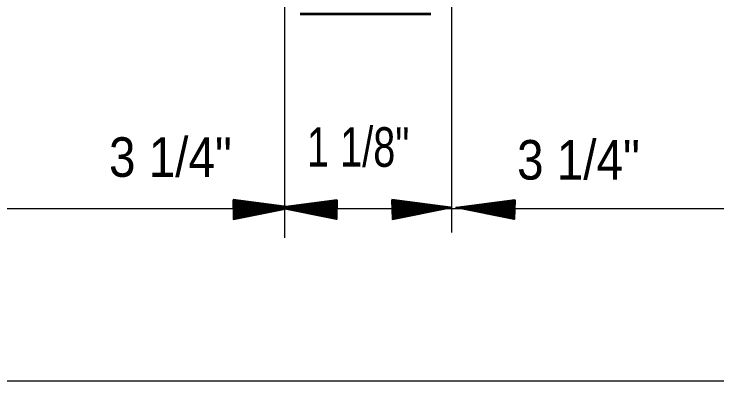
# Model space of a CAD drawing. Extents: x 895.6 to 930.4, y -2278.6 to -2254.7.
# Drawn here: x 901.427 to 903.71, y -2274.643 to -2273.45 of the extents above; entities that cross this region are included whole.
import ezdxf

# ---------------------------------------------------------------- set-up
doc = ezdxf.new("R2010")
doc.units = 0
doc.header["$LTSCALE"] = 0.051
doc.layers.add('1', color=7, linetype='Continuous', lineweight=70)
doc.layers.add('3', color=7, linetype='Continuous', lineweight=40)

msp = doc.modelspace()

# ---------------------------------------------------------------- hatches: boundary and pattern name
at = {"layer": '3'}
for points in [[(902.13817, -2274.05375), (902.14025, -2274.117), (902.32875, -2274.07892), (902.32875, -2274.07892)], [(902.13917, -2274.057), (902.141, -2274.11375), (902.31058, -2274.07958), (902.31058, -2274.07958)], [(902.14, -2274.05975), (902.14167, -2274.11092), (902.29433, -2274.08008), (902.29433, -2274.08008)], [(902.14083, -2274.06233), (902.14233, -2274.10825), (902.27967, -2274.08058), (902.27967, -2274.08058)], [(902.14142, -2274.06442), (902.14292, -2274.10583), (902.2665, -2274.081), (902.2665, -2274.081)], [(902.14225, -2274.06658), (902.14342, -2274.10383), (902.25467, -2274.08133), (902.25467, -2274.08133)], [(902.14267, -2274.06842), (902.14375, -2274.10208), (902.244, -2274.08183), (902.244, -2274.08183)], [(902.14325, -2274.07), (902.14417, -2274.10025), (902.23425, -2274.082), (902.23425, -2274.082)], [(902.14358, -2274.0715), (902.14458, -2274.09883), (902.22567, -2274.0825), (902.22567, -2274.0825)], [(902.14408, -2274.07292), (902.145, -2274.0975), (902.21792, -2274.08258), (902.21792, -2274.08258)], [(902.476, -2274.05375), (902.47392, -2274.117), (902.28542, -2274.07892), (902.28542, -2274.07892)], [(902.475, -2274.057), (902.47317, -2274.11375), (902.30358, -2274.07958), (902.30358, -2274.07958)], [(902.47417, -2274.05975), (902.4725, -2274.11092), (902.31983, -2274.08008), (902.31983, -2274.08008)], [(902.47333, -2274.06233), (902.47183, -2274.10825), (902.3345, -2274.08058), (902.3345, -2274.08058)], [(902.47275, -2274.06442), (902.47125, -2274.10583), (902.34767, -2274.081), (902.34767, -2274.081)], [(902.47192, -2274.06658), (902.47075, -2274.10383), (902.3595, -2274.08133), (902.3595, -2274.08133)], [(902.4715, -2274.06842), (902.47042, -2274.10208), (902.37017, -2274.08183), (902.37017, -2274.08183)], [(902.47092, -2274.07), (902.47, -2274.10025), (902.37992, -2274.082), (902.37992, -2274.082)], [(902.47058, -2274.0715), (902.46958, -2274.09883), (902.3885, -2274.0825), (902.3885, -2274.0825)], [(902.47008, -2274.07292), (902.46917, -2274.0975), (902.39625, -2274.08258), (902.39625, -2274.08258)], [(902.65433, -2274.05375), (902.65642, -2274.117), (902.84492, -2274.07892), (902.84492, -2274.07892)], [(902.65533, -2274.057), (902.65717, -2274.11375), (902.82675, -2274.07958), (902.82675, -2274.07958)], [(902.65617, -2274.05975), (902.65783, -2274.11092), (902.8105, -2274.08008), (902.8105, -2274.08008)], [(902.657, -2274.06233), (902.6585, -2274.10825), (902.79583, -2274.08058), (902.79583, -2274.08058)], [(902.65758, -2274.06442), (902.65908, -2274.10583), (902.78267, -2274.081), (902.78267, -2274.081)], [(902.65842, -2274.06658), (902.65958, -2274.10383), (902.77083, -2274.08133), (902.77083, -2274.08133)], [(902.65883, -2274.06842), (902.65992, -2274.10208), (902.76017, -2274.08183), (902.76017, -2274.08183)], [(902.65942, -2274.07), (902.66033, -2274.10025), (902.75042, -2274.082), (902.75042, -2274.082)], [(902.65975, -2274.0715), (902.66075, -2274.09883), (902.74183, -2274.0825), (902.74183, -2274.0825)], [(902.66025, -2274.07292), (902.66117, -2274.0975), (902.73408, -2274.08258), (902.73408, -2274.08258)], [(903.05358, -2274.05375), (903.0515, -2274.117), (902.863, -2274.07892), (902.863, -2274.07892)], [(903.05258, -2274.057), (903.05075, -2274.11375), (902.88117, -2274.07958), (902.88117, -2274.07958)], [(903.05175, -2274.05975), (903.05008, -2274.11092), (902.89742, -2274.08008), (902.89742, -2274.08008)], [(903.05092, -2274.06233), (903.04942, -2274.10825), (902.91208, -2274.08058), (902.91208, -2274.08058)], [(903.05033, -2274.06442), (903.04883, -2274.10583), (902.92525, -2274.081), (902.92525, -2274.081)], [(903.0495, -2274.06658), (903.04833, -2274.10383), (902.93708, -2274.08133), (902.93708, -2274.08133)], [(903.04908, -2274.06842), (903.048, -2274.10208), (902.94775, -2274.08183), (902.94775, -2274.08183)], [(903.0485, -2274.07), (903.04758, -2274.10025), (902.9575, -2274.082), (902.9575, -2274.082)], [(903.04817, -2274.0715), (903.04717, -2274.09883), (902.96608, -2274.0825), (902.96608, -2274.0825)], [(903.04767, -2274.07292), (903.04675, -2274.0975), (902.97383, -2274.08258), (902.97383, -2274.08258)], [(902.1445, -2274.07417), (902.14525, -2274.09608), (902.21083, -2274.08292), (902.21083, -2274.08292)], [(902.14475, -2274.07525), (902.1455, -2274.095), (902.20458, -2274.08325), (902.20458, -2274.08325)], [(902.14517, -2274.07617), (902.14567, -2274.09408), (902.19875, -2274.08333), (902.19875, -2274.08333)], [(902.1455, -2274.07717), (902.14592, -2274.09317), (902.19383, -2274.08342), (902.19383, -2274.08342)], [(902.14567, -2274.07792), (902.14617, -2274.09233), (902.18917, -2274.08358), (902.18917, -2274.08358)], [(902.14592, -2274.07858), (902.14625, -2274.09167), (902.18508, -2274.08392), (902.18508, -2274.08392)], [(902.14608, -2274.07925), (902.1465, -2274.09108), (902.18133, -2274.084), (902.18133, -2274.084)], [(902.14625, -2274.07992), (902.14658, -2274.09042), (902.17808, -2274.08408), (902.17808, -2274.08408)], [(902.1465, -2274.08025), (902.14675, -2274.08983), (902.17508, -2274.08408), (902.17508, -2274.08408)], [(902.14667, -2274.08067), (902.14692, -2274.08933), (902.17242, -2274.08408), (902.17242, -2274.08408)], [(902.14683, -2274.081), (902.14708, -2274.08867), (902.17, -2274.084), (902.17, -2274.084)], [(902.14683, -2274.08142), (902.14708, -2274.08833), (902.16783, -2274.08408), (902.16783, -2274.08408)], [(902.147, -2274.08183), (902.14725, -2274.088), (902.16583, -2274.08433), (902.16583, -2274.08433)], [(902.14708, -2274.082), (902.14733, -2274.08758), (902.16408, -2274.08425), (902.16408, -2274.08425)], [(902.46967, -2274.07417), (902.46892, -2274.09608), (902.40333, -2274.08292), (902.40333, -2274.08292)], [(902.46942, -2274.07525), (902.46867, -2274.095), (902.40958, -2274.08325), (902.40958, -2274.08325)], [(902.469, -2274.07617), (902.4685, -2274.09408), (902.41542, -2274.08333), (902.41542, -2274.08333)], [(902.46867, -2274.07717), (902.46825, -2274.09317), (902.42033, -2274.08342), (902.42033, -2274.08342)], [(902.4685, -2274.07792), (902.468, -2274.09233), (902.425, -2274.08358), (902.425, -2274.08358)], [(902.46825, -2274.07858), (902.46792, -2274.09167), (902.42908, -2274.08392), (902.42908, -2274.08392)], [(902.46808, -2274.07925), (902.46767, -2274.09108), (902.43283, -2274.084), (902.43283, -2274.084)], [(902.46792, -2274.07992), (902.46758, -2274.09042), (902.43608, -2274.08408), (902.43608, -2274.08408)], [(902.46767, -2274.08025), (902.46742, -2274.08983), (902.43908, -2274.08408), (902.43908, -2274.08408)], [(902.4675, -2274.08067), (902.46725, -2274.08933), (902.44175, -2274.08408), (902.44175, -2274.08408)], [(902.46733, -2274.081), (902.46708, -2274.08867), (902.44417, -2274.084), (902.44417, -2274.084)], [(902.46733, -2274.08142), (902.46708, -2274.08833), (902.44633, -2274.08408), (902.44633, -2274.08408)], [(902.46717, -2274.08183), (902.46692, -2274.088), (902.44833, -2274.08433), (902.44833, -2274.08433)], [(902.46708, -2274.082), (902.46683, -2274.08758), (902.45008, -2274.08425), (902.45008, -2274.08425)], [(902.66067, -2274.07417), (902.66142, -2274.09608), (902.727, -2274.08292), (902.727, -2274.08292)], [(902.66092, -2274.07525), (902.66167, -2274.095), (902.72075, -2274.08325), (902.72075, -2274.08325)], [(902.66133, -2274.07617), (902.66183, -2274.09408), (902.71492, -2274.08333), (902.71492, -2274.08333)], [(902.66167, -2274.07717), (902.66208, -2274.09317), (902.71, -2274.08342), (902.71, -2274.08342)], [(902.66183, -2274.07792), (902.66233, -2274.09233), (902.70533, -2274.08358), (902.70533, -2274.08358)], [(902.66208, -2274.07858), (902.66242, -2274.09167), (902.70125, -2274.08392), (902.70125, -2274.08392)], [(902.66225, -2274.07925), (902.66267, -2274.09108), (902.6975, -2274.084), (902.6975, -2274.084)], [(902.66242, -2274.07992), (902.66275, -2274.09042), (902.69425, -2274.08408), (902.69425, -2274.08408)], [(902.66267, -2274.08025), (902.66292, -2274.08983), (902.69125, -2274.08408), (902.69125, -2274.08408)], [(902.66283, -2274.08067), (902.66308, -2274.08933), (902.68858, -2274.08408), (902.68858, -2274.08408)], [(902.663, -2274.081), (902.66325, -2274.08867), (902.68617, -2274.084), (902.68617, -2274.084)], [(902.663, -2274.08142), (902.66325, -2274.08833), (902.684, -2274.08408), (902.684, -2274.08408)], [(902.66317, -2274.08183), (902.66342, -2274.088), (902.682, -2274.08433), (902.682, -2274.08433)], [(902.66325, -2274.082), (902.6635, -2274.08758), (902.68025, -2274.08425), (902.68025, -2274.08425)], [(903.04725, -2274.07417), (903.0465, -2274.09608), (902.98092, -2274.08292), (902.98092, -2274.08292)], [(903.047, -2274.07525), (903.04625, -2274.095), (902.98717, -2274.08325), (902.98717, -2274.08325)], [(903.04658, -2274.07617), (903.04608, -2274.09408), (902.993, -2274.08333), (902.993, -2274.08333)], [(903.04625, -2274.07717), (903.04583, -2274.09317), (902.99792, -2274.08342), (902.99792, -2274.08342)], [(903.04608, -2274.07792), (903.04558, -2274.09233), (903.00258, -2274.08358), (903.00258, -2274.08358)], [(903.04583, -2274.07858), (903.0455, -2274.09167), (903.00667, -2274.08392), (903.00667, -2274.08392)], [(903.04567, -2274.07925), (903.04525, -2274.09108), (903.01042, -2274.084), (903.01042, -2274.084)], [(903.0455, -2274.07992), (903.04517, -2274.09042), (903.01367, -2274.08408), (903.01367, -2274.08408)], [(903.04525, -2274.08025), (903.045, -2274.08983), (903.01667, -2274.08408), (903.01667, -2274.08408)], [(903.04508, -2274.08067), (903.04483, -2274.08933), (903.01933, -2274.08408), (903.01933, -2274.08408)], [(903.04492, -2274.081), (903.04467, -2274.08867), (903.02175, -2274.084), (903.02175, -2274.084)], [(903.04492, -2274.08142), (903.04467, -2274.08833), (903.02392, -2274.08408), (903.02392, -2274.08408)], [(903.04475, -2274.08183), (903.0445, -2274.088), (903.02592, -2274.08433), (903.02592, -2274.08433)], [(903.04467, -2274.082), (903.04442, -2274.08758), (903.02767, -2274.08425), (903.02767, -2274.08425)]]:
    msp.add_hatch(color=256, dxfattribs=at).paths.add_polyline_path(points)

# ---------------------------------------------------------------- linework, layer by layer
at = {"layer": '1', "lineweight": 25}
for p, q in [((902.30508, -2273.35175), (902.30508, -2274.17808)), ((902.84783, -2273.35175), (902.84783, -2274.16025)), ((900.23575, -2274.08225), (904.02683, -2274.08225)), ((900.23575, -2274.64308), (907.81792, -2274.64308))]:
    msp.add_line(p, q, dxfattribs=at)
at = {"layer": '1', "lineweight": 53}
msp.add_line((902.78058, -2273.45075), (902.3565, -2273.45075), dxfattribs=at)
at = {"layer": '3'}
for points in [[(902.13817, -2274.05375), (902.14025, -2274.117), (902.32875, -2274.07892), (902.32875, -2274.07892)], [(902.13917, -2274.057), (902.141, -2274.11375), (902.31058, -2274.07958), (902.31058, -2274.07958)], [(902.14, -2274.05975), (902.14167, -2274.11092), (902.29433, -2274.08008), (902.29433, -2274.08008)], [(902.14083, -2274.06233), (902.14233, -2274.10825), (902.27967, -2274.08058), (902.27967, -2274.08058)], [(902.14142, -2274.06442), (902.14292, -2274.10583), (902.2665, -2274.081), (902.2665, -2274.081)], [(902.14225, -2274.06658), (902.14342, -2274.10383), (902.25467, -2274.08133), (902.25467, -2274.08133)], [(902.14267, -2274.06842), (902.14375, -2274.10208), (902.244, -2274.08183), (902.244, -2274.08183)], [(902.14325, -2274.07), (902.14417, -2274.10025), (902.23425, -2274.082), (902.23425, -2274.082)], [(902.14358, -2274.0715), (902.14458, -2274.09883), (902.22567, -2274.0825), (902.22567, -2274.0825)], [(902.14408, -2274.07292), (902.145, -2274.0975), (902.21792, -2274.08258), (902.21792, -2274.08258)], [(902.476, -2274.05375), (902.47392, -2274.117), (902.28542, -2274.07892), (902.28542, -2274.07892)], [(902.475, -2274.057), (902.47317, -2274.11375), (902.30358, -2274.07958), (902.30358, -2274.07958)], [(902.47417, -2274.05975), (902.4725, -2274.11092), (902.31983, -2274.08008), (902.31983, -2274.08008)], [(902.47333, -2274.06233), (902.47183, -2274.10825), (902.3345, -2274.08058), (902.3345, -2274.08058)], [(902.47275, -2274.06442), (902.47125, -2274.10583), (902.34767, -2274.081), (902.34767, -2274.081)], [(902.47192, -2274.06658), (902.47075, -2274.10383), (902.3595, -2274.08133), (902.3595, -2274.08133)], [(902.4715, -2274.06842), (902.47042, -2274.10208), (902.37017, -2274.08183), (902.37017, -2274.08183)], [(902.47092, -2274.07), (902.47, -2274.10025), (902.37992, -2274.082), (902.37992, -2274.082)], [(902.47058, -2274.0715), (902.46958, -2274.09883), (902.3885, -2274.0825), (902.3885, -2274.0825)], [(902.47008, -2274.07292), (902.46917, -2274.0975), (902.39625, -2274.08258), (902.39625, -2274.08258)], [(902.65433, -2274.05375), (902.65642, -2274.117), (902.84492, -2274.07892), (902.84492, -2274.07892)], [(902.65533, -2274.057), (902.65717, -2274.11375), (902.82675, -2274.07958), (902.82675, -2274.07958)], [(902.65617, -2274.05975), (902.65783, -2274.11092), (902.8105, -2274.08008), (902.8105, -2274.08008)], [(902.657, -2274.06233), (902.6585, -2274.10825), (902.79583, -2274.08058), (902.79583, -2274.08058)], [(902.65758, -2274.06442), (902.65908, -2274.10583), (902.78267, -2274.081), (902.78267, -2274.081)], [(902.65842, -2274.06658), (902.65958, -2274.10383), (902.77083, -2274.08133), (902.77083, -2274.08133)], [(902.65883, -2274.06842), (902.65992, -2274.10208), (902.76017, -2274.08183), (902.76017, -2274.08183)], [(902.65942, -2274.07), (902.66033, -2274.10025), (902.75042, -2274.082), (902.75042, -2274.082)], [(902.65975, -2274.0715), (902.66075, -2274.09883), (902.74183, -2274.0825), (902.74183, -2274.0825)], [(902.66025, -2274.07292), (902.66117, -2274.0975), (902.73408, -2274.08258), (902.73408, -2274.08258)], [(903.05358, -2274.05375), (903.0515, -2274.117), (902.863, -2274.07892), (902.863, -2274.07892)], [(903.05258, -2274.057), (903.05075, -2274.11375), (902.88117, -2274.07958), (902.88117, -2274.07958)], [(903.05175, -2274.05975), (903.05008, -2274.11092), (902.89742, -2274.08008), (902.89742, -2274.08008)], [(903.05092, -2274.06233), (903.04942, -2274.10825), (902.91208, -2274.08058), (902.91208, -2274.08058)], [(903.05033, -2274.06442), (903.04883, -2274.10583), (902.92525, -2274.081), (902.92525, -2274.081)], [(903.0495, -2274.06658), (903.04833, -2274.10383), (902.93708, -2274.08133), (902.93708, -2274.08133)], [(903.04908, -2274.06842), (903.048, -2274.10208), (902.94775, -2274.08183), (902.94775, -2274.08183)], [(903.0485, -2274.07), (903.04758, -2274.10025), (902.9575, -2274.082), (902.9575, -2274.082)], [(903.04817, -2274.0715), (903.04717, -2274.09883), (902.96608, -2274.0825), (902.96608, -2274.0825)], [(903.04767, -2274.07292), (903.04675, -2274.0975), (902.97383, -2274.08258), (902.97383, -2274.08258)], [(902.1445, -2274.07417), (902.14525, -2274.09608), (902.21083, -2274.08292), (902.21083, -2274.08292)], [(902.14475, -2274.07525), (902.1455, -2274.095), (902.20458, -2274.08325), (902.20458, -2274.08325)], [(902.14517, -2274.07617), (902.14567, -2274.09408), (902.19875, -2274.08333), (902.19875, -2274.08333)], [(902.1455, -2274.07717), (902.14592, -2274.09317), (902.19383, -2274.08342), (902.19383, -2274.08342)], [(902.14567, -2274.07792), (902.14617, -2274.09233), (902.18917, -2274.08358), (902.18917, -2274.08358)], [(902.14592, -2274.07858), (902.14625, -2274.09167), (902.18508, -2274.08392), (902.18508, -2274.08392)], [(902.14608, -2274.07925), (902.1465, -2274.09108), (902.18133, -2274.084), (902.18133, -2274.084)], [(902.14625, -2274.07992), (902.14658, -2274.09042), (902.17808, -2274.08408), (902.17808, -2274.08408)], [(902.1465, -2274.08025), (902.14675, -2274.08983), (902.17508, -2274.08408), (902.17508, -2274.08408)], [(902.14667, -2274.08067), (902.14692, -2274.08933), (902.17242, -2274.08408), (902.17242, -2274.08408)], [(902.14683, -2274.081), (902.14708, -2274.08867), (902.17, -2274.084), (902.17, -2274.084)], [(902.14683, -2274.08142), (902.14708, -2274.08833), (902.16783, -2274.08408), (902.16783, -2274.08408)], [(902.147, -2274.08183), (902.14725, -2274.088), (902.16583, -2274.08433), (902.16583, -2274.08433)], [(902.14708, -2274.082), (902.14733, -2274.08758), (902.16408, -2274.08425), (902.16408, -2274.08425)], [(902.46967, -2274.07417), (902.46892, -2274.09608), (902.40333, -2274.08292), (902.40333, -2274.08292)], [(902.46942, -2274.07525), (902.46867, -2274.095), (902.40958, -2274.08325), (902.40958, -2274.08325)], [(902.469, -2274.07617), (902.4685, -2274.09408), (902.41542, -2274.08333), (902.41542, -2274.08333)], [(902.46867, -2274.07717), (902.46825, -2274.09317), (902.42033, -2274.08342), (902.42033, -2274.08342)], [(902.4685, -2274.07792), (902.468, -2274.09233), (902.425, -2274.08358), (902.425, -2274.08358)], [(902.46825, -2274.07858), (902.46792, -2274.09167), (902.42908, -2274.08392), (902.42908, -2274.08392)], [(902.46808, -2274.07925), (902.46767, -2274.09108), (902.43283, -2274.084), (902.43283, -2274.084)], [(902.46792, -2274.07992), (902.46758, -2274.09042), (902.43608, -2274.08408), (902.43608, -2274.08408)], [(902.46767, -2274.08025), (902.46742, -2274.08983), (902.43908, -2274.08408), (902.43908, -2274.08408)], [(902.4675, -2274.08067), (902.46725, -2274.08933), (902.44175, -2274.08408), (902.44175, -2274.08408)], [(902.46733, -2274.081), (902.46708, -2274.08867), (902.44417, -2274.084), (902.44417, -2274.084)], [(902.46733, -2274.08142), (902.46708, -2274.08833), (902.44633, -2274.08408), (902.44633, -2274.08408)], [(902.46717, -2274.08183), (902.46692, -2274.088), (902.44833, -2274.08433), (902.44833, -2274.08433)], [(902.46708, -2274.082), (902.46683, -2274.08758), (902.45008, -2274.08425), (902.45008, -2274.08425)], [(902.66067, -2274.07417), (902.66142, -2274.09608), (902.727, -2274.08292), (902.727, -2274.08292)], [(902.66092, -2274.07525), (902.66167, -2274.095), (902.72075, -2274.08325), (902.72075, -2274.08325)], [(902.66133, -2274.07617), (902.66183, -2274.09408), (902.71492, -2274.08333), (902.71492, -2274.08333)], [(902.66167, -2274.07717), (902.66208, -2274.09317), (902.71, -2274.08342), (902.71, -2274.08342)], [(902.66183, -2274.07792), (902.66233, -2274.09233), (902.70533, -2274.08358), (902.70533, -2274.08358)], [(902.66208, -2274.07858), (902.66242, -2274.09167), (902.70125, -2274.08392), (902.70125, -2274.08392)], [(902.66225, -2274.07925), (902.66267, -2274.09108), (902.6975, -2274.084), (902.6975, -2274.084)], [(902.66242, -2274.07992), (902.66275, -2274.09042), (902.69425, -2274.08408), (902.69425, -2274.08408)], [(902.66267, -2274.08025), (902.66292, -2274.08983), (902.69125, -2274.08408), (902.69125, -2274.08408)], [(902.66283, -2274.08067), (902.66308, -2274.08933), (902.68858, -2274.08408), (902.68858, -2274.08408)], [(902.663, -2274.081), (902.66325, -2274.08867), (902.68617, -2274.084), (902.68617, -2274.084)], [(902.663, -2274.08142), (902.66325, -2274.08833), (902.684, -2274.08408), (902.684, -2274.08408)], [(902.66317, -2274.08183), (902.66342, -2274.088), (902.682, -2274.08433), (902.682, -2274.08433)], [(902.66325, -2274.082), (902.6635, -2274.08758), (902.68025, -2274.08425), (902.68025, -2274.08425)], [(903.04725, -2274.07417), (903.0465, -2274.09608), (902.98092, -2274.08292), (902.98092, -2274.08292)], [(903.047, -2274.07525), (903.04625, -2274.095), (902.98717, -2274.08325), (902.98717, -2274.08325)], [(903.04658, -2274.07617), (903.04608, -2274.09408), (902.993, -2274.08333), (902.993, -2274.08333)], [(903.04625, -2274.07717), (903.04583, -2274.09317), (902.99792, -2274.08342), (902.99792, -2274.08342)], [(903.04608, -2274.07792), (903.04558, -2274.09233), (903.00258, -2274.08358), (903.00258, -2274.08358)], [(903.04583, -2274.07858), (903.0455, -2274.09167), (903.00667, -2274.08392), (903.00667, -2274.08392)], [(903.04567, -2274.07925), (903.04525, -2274.09108), (903.01042, -2274.084), (903.01042, -2274.084)], [(903.0455, -2274.07992), (903.04517, -2274.09042), (903.01367, -2274.08408), (903.01367, -2274.08408)], [(903.04525, -2274.08025), (903.045, -2274.08983), (903.01667, -2274.08408), (903.01667, -2274.08408)], [(903.04508, -2274.08067), (903.04483, -2274.08933), (903.01933, -2274.08408), (903.01933, -2274.08408)], [(903.04492, -2274.081), (903.04467, -2274.08867), (903.02175, -2274.084), (903.02175, -2274.084)], [(903.04492, -2274.08142), (903.04467, -2274.08833), (903.02392, -2274.08408), (903.02392, -2274.08408)], [(903.04475, -2274.08183), (903.0445, -2274.088), (903.02592, -2274.08433), (903.02592, -2274.08433)], [(903.04467, -2274.082), (903.04442, -2274.08758), (903.02767, -2274.08425), (903.02767, -2274.08425)]]:
    msp.add_lwpolyline(points, close=True, dxfattribs=at)

# ---------------------------------------------------------------- texts
at = {"layer": '1'}
for s, width, p in [('1 1/8"', 0.75, (902.3785, -2273.94667)), ('3 1/4"', 0.9, (901.73525, -2273.97933)), ('3 1/4"', 0.9, (903.061, -2273.98825))]:
    msp.add_text(s, height=0.1286, dxfattribs=dict(at, width=width)).set_placement(p)

doc.saveas('drawing.dxf')
